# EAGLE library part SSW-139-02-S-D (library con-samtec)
THROUGH-HOLE .025" SQ POST SOCKET Source: Samtec SSW.pdf
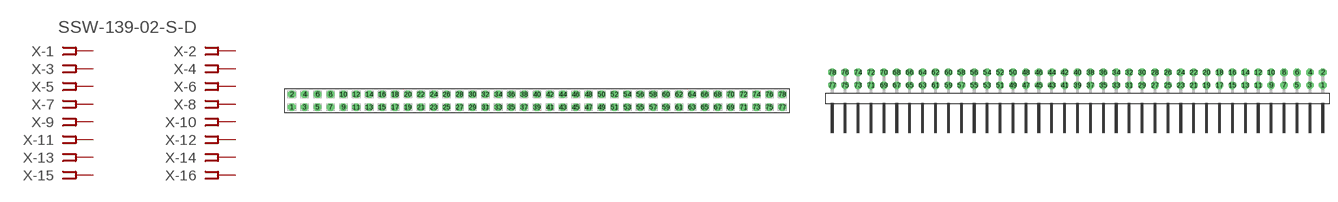
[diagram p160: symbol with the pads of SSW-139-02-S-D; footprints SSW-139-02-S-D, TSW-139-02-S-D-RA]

Designator prefix X; gates -1=FPINV -2=FPIN -3=FPIN -4=FPIN -5=FPIN -6=FPIN -7=FPIN -8=FPIN -9=FPIN -10=FPIN -11=FPIN -12=FPIN -13=FPIN -14=FPIN -15=FPIN -16=FPIN -17=FPIN -18=FPIN -19=FPIN -20=FPIN -21=FPIN -22=FPIN -23=FPIN -24=FPIN -25=FPIN -26=FPIN -27=FPIN -28=FPIN -29=FPIN -30=FPIN -31=FPIN -32=FPIN -33=FPIN -34=FPIN -35=FPIN -36=FPIN -37=FPIN -38=FPIN -39=FPIN -40=FPIN -41=FPIN -42=FPIN -43=FPIN -44=FPIN -45=FPIN -46=FPIN -47=FPIN -48=FPIN -49=FPIN -50=FPIN -51=FPIN -52=FPIN -53=FPIN -54=FPIN -55=FPIN -56=FPIN -57=FPIN -58=FPIN -59=FPIN -60=FPIN -61=FPIN -62=FPIN -63=FPIN -64=FPIN -65=FPIN -66=FPIN -67=FPIN -68=FPIN -69=FPIN -70=FPIN -71=FPIN -72=FPIN -73=FPIN -74=FPIN -75=FPIN -76=FPIN -77=FPIN -78=FPIN

## SSW-139-02-S-D (OC_FARNELL: unknown; OC_NEWARK: unknown)  [SSW-139-02-S-D]
1  -1:1  pas
2  -2:1  pas
3  -3:1  pas
4  -4:1  pas
5  -5:1  pas
6  -6:1  pas
7  -7:1  pas
8  -8:1  pas
9  -9:1  pas
10  -10:1  pas
11  -11:1  pas
12  -12:1  pas
13  -13:1  pas
14  -14:1  pas
15  -15:1  pas
16  -16:1  pas
17  -17:1  pas
18  -18:1  pas
19  -19:1  pas
20  -20:1  pas
21  -21:1  pas
22  -22:1  pas
23  -23:1  pas
24  -24:1  pas
25  -25:1  pas
26  -26:1  pas
27  -27:1  pas
28  -28:1  pas
29  -29:1  pas
30  -30:1  pas
31  -31:1  pas
32  -32:1  pas
33  -33:1  pas
34  -34:1  pas
35  -35:1  pas
36  -36:1  pas
37  -37:1  pas
38  -38:1  pas
39  -39:1  pas
40  -40:1  pas
41  -41:1  pas
42  -42:1  pas
43  -43:1  pas
44  -44:1  pas
45  -45:1  pas
46  -46:1  pas
47  -47:1  pas
48  -48:1  pas
49  -49:1  pas
50  -50:1  pas
51  -51:1  pas
52  -52:1  pas
53  -53:1  pas
54  -54:1  pas
55  -55:1  pas
56  -56:1  pas
57  -57:1  pas
58  -58:1  pas
59  -59:1  pas
60  -60:1  pas
61  -61:1  pas
62  -62:1  pas
63  -63:1  pas
64  -64:1  pas
65  -65:1  pas
66  -66:1  pas
67  -67:1  pas
68  -68:1  pas
69  -69:1  pas
70  -70:1  pas
71  -71:1  pas
72  -72:1  pas
73  -73:1  pas
74  -74:1  pas
75  -75:1  pas
76  -76:1  pas
77  -77:1  pas
78  -78:1  pas

## SSW-139-02-S-D-RA (MPN: SSW-139-02-S-D-RA; OC_FARNELL: unknown; OC_NEWARK: 11P9942)  [TSW-139-02-S-D-RA]
Pads as for SSW-139-02-S-D

## Footprint SSW-139-02-S-D (pad centres in mm)
THROUGH-HOLE .025" SQ POST SOCKET Source: Samtec SSW.pdf
drill 1 pad 1.5 octagon: 1 -48.26,-1.27; 2 -48.26,1.27; 3 -45.72,-1.27; 4 -45.72,1.27; 5 -43.18,-1.27; 6 -43.18,1.27; 7 -40.64,-1.27; 8 -40.64,1.27; 9 -38.1,-1.27; 10 -38.1,1.27; 11 -35.56,-1.27; 12 -35.56,1.27; 13 -33.02,-1.27; 14 -33.02,1.27; 15 -30.48,-1.27; 16 -30.48,1.27; 17 -27.94,-1.27; 18 -27.94,1.27; 19 -25.4,-1.27; 20 -25.4,1.27; 21 -22.86,-1.27; 22 -22.86,1.27; 23 -20.32,-1.27; 24 -20.32,1.27; 25 -17.78,-1.27; 26 -17.78,1.27; 27 -15.24,-1.27; 28 -15.24,1.27; 29 -12.7,-1.27; 30 -12.7,1.27; 31 -10.16,-1.27; 32 -10.16,1.27; 33 -7.62,-1.27; 34 -7.62,1.27; 35 -5.08,-1.27; 36 -5.08,1.27; 37 -2.54,-1.27; 38 -2.54,1.27; 39 0,-1.27; 40 0,1.27; 41 2.54,-1.27; 42 2.54,1.27; 43 5.08,-1.27; 44 5.08,1.27; 45 7.62,-1.27; 46 7.62,1.27; 47 10.16,-1.27; 48 10.16,1.27; 49 12.7,-1.27; 50 12.7,1.27; 51 15.24,-1.27; 52 15.24,1.27; 53 17.78,-1.27; 54 17.78,1.27; 55 20.32,-1.27; 56 20.32,1.27; 57 22.86,-1.27; 58 22.86,1.27; 59 25.4,-1.27; 60 25.4,1.27; 61 27.94,-1.27; 62 27.94,1.27; 63 30.48,-1.27; 64 30.48,1.27; 65 33.02,-1.27; 66 33.02,1.27; 67 35.56,-1.27; 68 35.56,1.27; 69 38.1,-1.27; 70 38.1,1.27; 71 40.64,-1.27; 72 40.64,1.27; 73 43.18,-1.27; 74 43.18,1.27; 75 45.72,-1.27; 76 45.72,1.27; 77 48.26,-1.27; 78 48.26,1.27

## Footprint TSW-139-02-S-D-RA (pad centres in mm)
THROUGH-HOLE .025" SQ POST HEADER Source: Samtec TSW.pdf
drill 1 pad 1.5 octagon: 1 48.26,1.524; 2 48.26,4.064; 3 45.72,1.524; 4 45.72,4.064; 5 43.18,1.524; 6 43.18,4.064; 7 40.64,1.524; 8 40.64,4.064; 9 38.1,1.524; 10 38.1,4.064; 11 35.56,1.524; 12 35.56,4.064; 13 33.02,1.524; 14 33.02,4.064; 15 30.48,1.524; 16 30.48,4.064; 17 27.94,1.524; 18 27.94,4.064; 19 25.4,1.524; 20 25.4,4.064; 21 22.86,1.524; 22 22.86,4.064; 23 20.32,1.524; 24 20.32,4.064; 25 17.78,1.524; 26 17.78,4.064; 27 15.24,1.524; 28 15.24,4.064; 29 12.7,1.524; 30 12.7,4.064; 31 10.16,1.524; 32 10.16,4.064; 33 7.62,1.524; 34 7.62,4.064; 35 5.08,1.524; 36 5.08,4.064; 37 2.54,1.524; 38 2.54,4.064; 39 0,1.524; 40 0,4.064; 41 -2.54,1.524; 42 -2.54,4.064; 43 -5.08,1.524; 44 -5.08,4.064; 45 -7.62,1.524; 46 -7.62,4.064; 47 -10.16,1.524; 48 -10.16,4.064; 49 -12.7,1.524; 50 -12.7,4.064; 51 -15.24,1.524; 52 -15.24,4.064; 53 -17.78,1.524; 54 -17.78,4.064; 55 -20.32,1.524; 56 -20.32,4.064; 57 -22.86,1.524; 58 -22.86,4.064; 59 -25.4,1.524; 60 -25.4,4.064; 61 -27.94,1.524; 62 -27.94,4.064; 63 -30.48,1.524; 64 -30.48,4.064; 65 -33.02,1.524; 66 -33.02,4.064; 67 -35.56,1.524; 68 -35.56,4.064; 69 -38.1,1.524; 70 -38.1,4.064; 71 -40.64,1.524; 72 -40.64,4.064; 73 -43.18,1.524; 74 -43.18,4.064; 75 -45.72,1.524; 76 -45.72,4.064; 77 -48.26,1.524; 78 -48.26,4.064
